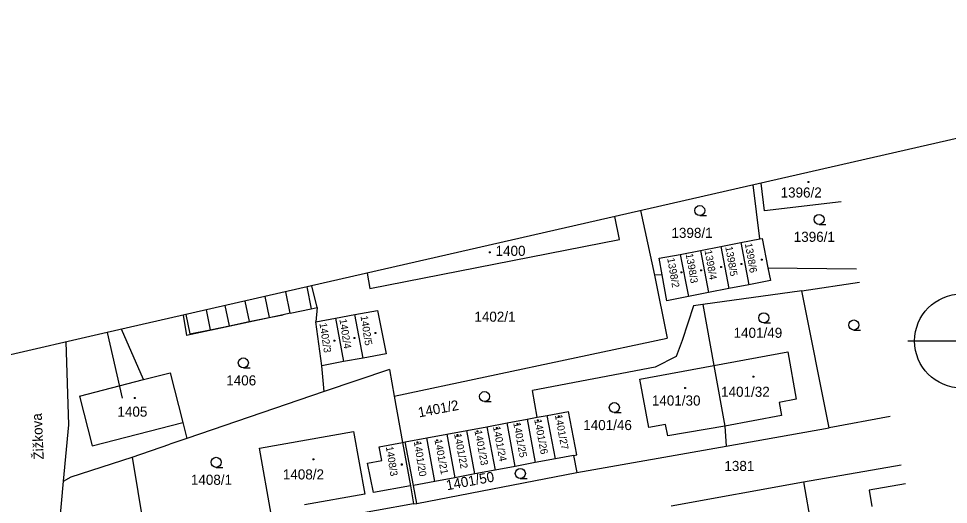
# Model space of a CAD drawing. Extents: x -805730 to -804640, y -1150889 to -1150366.
# Drawn here: x -804924.5 to -804785.9, y -1150438.4 to -1150366 of the extents above; entities that cross this region are included whole.
import ezdxf

# ---------------------------------------------------------------- set-up
doc = ezdxf.new("R2010")
doc.units = 0
for name, color, linetype in [('Default', 7, 'Continuous'), ('formát', 7, 'Continuous'), ('kn_celek - Cisla pozemkovych parcel', 7, 'Continuous'), ('kn_celek - Cisla stavebnich parcel', 7, 'Continuous'), ('kn_celek - Dalsi prvky mapy popis', 7, 'Continuous'), ('kn_celek - Hranice parcel', 7, 'Continuous'), ('kn_celek - Vnitrni kresby', 7, 'Continuous'), ('kn_celek - Znacky budov', 7, 'Continuous'), ('kn_celek - Znacky kultur', 7, 'Continuous')]:
    doc.layers.add(name, color=color, linetype=linetype)

# ---------------------------------------------------------------- blocks, each defined once
blk = doc.blocks.new('304')
at = {"layer": 'Default'}
blk.add_line((-0.1, 0), (9.9, 0), dxfattribs=at)
blk.add_circle((-0.1, 7.5), 7.5, dxfattribs=at)
blk = doc.blocks.new('402')
at = {"layer": 'Default'}
for p, q in [((-0.8, 0.8), (0.7, 0.8)), ((-0.8, 0.8), (-0.8, -0.7)), ((0.7, 0.8), (0.7, -0.7)), ((0.7, -0.7), (-0.8, -0.7))]:
    blk.add_line(p, q, dxfattribs=at)

msp = doc.modelspace()

# ---------------------------------------------------------------- linework, layer by layer
at = {"layer": 'formát'}
for p, q in [((-804706.6, -1150365.97), (-804911.33, -1150412.76)), ((-804911.33, -1150412.76), (-805116.05, -1150459.54)), ((-804911.33, -1150412.76), (-804909.1, -1150422.5)), ((-804791.95, -1150414), (-804775.95, -1150414))]:
    msp.add_line(p, q, dxfattribs=at)
msp.add_circle((-804783.95, -1150414), 7, dxfattribs=at)
at = {"layer": 'kn_celek - Hranice parcel'}
for p, q in [((-804814, -1150398.79), (-804815.01, -1150390.74)), ((-804813.34, -1150394.63), (-804813.84, -1150390.47)), ((-804801.9, -1150393.26), (-804813.34, -1150394.63)), ((-804831.82, -1150394.58), (-804829.73, -1150404.21)), ((-804834.96, -1150398.88), (-804835.65, -1150395.46)), ((-804872.14, -1150406.19), (-804834.96, -1150398.88)), ((-804816.85, -1150399.35), (-804814, -1150398.79)), ((-804814, -1150398.79), (-804813.67, -1150398.72)), ((-804813.67, -1150398.72), (-804812.81, -1150403.09)), ((-804822.88, -1150400.52), (-804819.85, -1150399.93)), ((-804819.85, -1150399.93), (-804816.85, -1150399.35)), ((-804819.85, -1150399.93), (-804818.64, -1150406.19)), ((-804816.85, -1150399.35), (-804815.64, -1150405.61)), ((-804829.01, -1150401.67), (-804825.87, -1150401.09)), ((-804828.57, -1150404.13), (-804829.01, -1150401.67)), ((-804825.87, -1150401.09), (-804822.88, -1150400.52)), ((-804825.87, -1150401.09), (-804824.66, -1150407.36)), ((-804822.88, -1150400.52), (-804821.67, -1150406.78)), ((-804812.81, -1150403.09), (-804808.43, -1150403.14)), ((-804812.81, -1150403.09), (-804812.44, -1150405)), ((-804808.43, -1150403.14), (-804799.62, -1150403.24)), ((-804872.57, -1150403.9), (-804872.14, -1150406.19)), ((-804828.57, -1150404.13), (-804829.73, -1150404.21)), ((-804829.73, -1150404.21), (-804827.82, -1150413.58)), ((-804827.86, -1150408.03), (-804828.57, -1150404.13)), ((-804881.57, -1150405.95), (-804880.9, -1150409.19)), ((-804880.03, -1150409), (-804880.8, -1150405.78)), ((-804815.64, -1150405.61), (-804818.64, -1150406.19)), ((-804812.44, -1150405), (-804815.64, -1150405.61)), ((-804807.76, -1150406.52), (-804799.16, -1150405.25)), ((-804887.83, -1150407.38), (-804887.18, -1150410.5)), ((-804884.02, -1150409.86), (-804884.69, -1150406.67)), ((-804824.66, -1150407.36), (-804827.86, -1150408.03)), ((-804821.67, -1150406.78), (-804824.66, -1150407.36)), ((-804807.76, -1150406.52), (-804822.52, -1150408.58)), ((-804818.64, -1150406.19), (-804821.67, -1150406.78)), ((-804803.69, -1150426.95), (-804807.76, -1150406.52)), ((-804893.09, -1150411.73), (-804893.71, -1150408.73)), ((-804890.78, -1150408.06), (-804890.14, -1150411.12)), ((-804823.89, -1150408.77), (-804825.57, -1150413.91)), ((-804822.52, -1150408.58), (-804823.89, -1150408.77)), ((-804822.52, -1150408.58), (-804820.89, -1150417.64)), ((-804900, -1150410.17), (-804899.47, -1150413.17)), ((-804899.59, -1150410.07), (-804898.99, -1150412.96)), ((-804885.07, -1150410.08), (-804899.47, -1150413.17)), ((-804896.55, -1150409.38), (-804895.94, -1150412.32)), ((-804887.18, -1150410.5), (-804885.07, -1150410.08)), ((-804884.02, -1150409.86), (-804885.07, -1150410.08)), ((-804884.02, -1150409.86), (-804880.89, -1150409.22)), ((-804880.9, -1150409.19), (-804880.03, -1150409)), ((-804880.9, -1150409.19), (-804880.89, -1150409.22)), ((-804880.03, -1150409), (-804880.21, -1150411.14)), ((-804877.29, -1150410.62), (-804874.37, -1150410.07)), ((-804874.37, -1150410.07), (-804870.99, -1150409.45)), ((-804873.16, -1150416.54), (-804874.37, -1150410.07)), ((-804870.99, -1150409.45), (-804869.72, -1150415.9)), ((-804893.09, -1150411.73), (-804890.14, -1150411.12)), ((-804890.14, -1150411.12), (-804887.18, -1150410.5)), ((-804880.21, -1150411.14), (-804877.29, -1150410.62)), ((-804879.29, -1150417.68), (-804880.21, -1150411.14)), ((-804877.29, -1150410.62), (-804876.08, -1150417.08)), ((-804905.91, -1150419.76), (-804909.16, -1150412.26)), ((-804898.99, -1150412.96), (-804895.94, -1150412.32)), ((-804895.94, -1150412.32), (-804893.09, -1150411.73)), ((-804917.04, -1150426.49), (-804917.43, -1150414.15)), ((-804868.52, -1150422.21), (-804827.82, -1150413.58)), ((-804825.57, -1150413.91), (-804826.47, -1150416.31)), ((-804820.89, -1150417.64), (-804809.86, -1150415.61)), ((-804809.86, -1150415.61), (-804808.62, -1150422.68)), ((-804876.08, -1150417.08), (-804879.29, -1150417.68)), ((-804873.16, -1150416.54), (-804876.08, -1150417.08)), ((-804869.72, -1150415.9), (-804873.16, -1150416.54)), ((-804826.47, -1150416.31), (-804829.6, -1150417.89)), ((-804878.94, -1150421.54), (-804879.29, -1150417.68)), ((-804869.23, -1150418.27), (-804878.94, -1150421.54)), ((-804869.23, -1150418.27), (-804868.52, -1150422.21)), ((-804829.6, -1150417.89), (-804847.92, -1150421.36)), ((-804831.91, -1150419.67), (-804820.89, -1150417.64)), ((-804820.89, -1150417.64), (-804819.25, -1150426.68)), ((-804905.91, -1150419.76), (-804901.92, -1150418.74)), ((-804901.92, -1150418.74), (-804900.03, -1150426.14)), ((-804830.58, -1150426.89), (-804831.91, -1150419.67)), ((-804878.94, -1150421.54), (-804899.42, -1150428.51)), ((-804868.52, -1150422.21), (-804867.28, -1150429.13)), ((-804847.21, -1150425.37), (-804847.92, -1150421.36)), ((-804808.62, -1150422.68), (-804811.11, -1150423.15)), ((-804811.11, -1150423.15), (-804810.77, -1150425.1)), ((-804848.71, -1150425.65), (-804847.21, -1150425.37)), ((-804847.21, -1150425.37), (-804845.71, -1150425.08)), ((-804845.71, -1150425.08), (-804842.53, -1150424.5)), ((-804844.5, -1150431.56), (-804845.71, -1150425.08)), ((-804841.29, -1150430.95), (-804842.53, -1150424.5)), ((-804810.77, -1150425.1), (-804819.25, -1150426.68)), ((-804794.59, -1150425.24), (-804803.69, -1150426.95)), ((-804917.82, -1150434.88), (-804917.04, -1150426.49)), ((-804900.03, -1150426.14), (-804899.42, -1150428.51)), ((-804857.69, -1150427.33), (-804854.69, -1150426.77)), ((-804854.69, -1150426.77), (-804851.7, -1150426.21)), ((-804854.69, -1150426.77), (-804853.48, -1150433.25)), ((-804851.7, -1150426.21), (-804848.71, -1150425.65)), ((-804850.49, -1150432.68), (-804851.7, -1150426.21)), ((-804848.71, -1150425.65), (-804847.49, -1150432.12)), ((-804828.08, -1150426.43), (-804830.58, -1150426.89)), ((-804827.74, -1150428.12), (-804828.08, -1150426.43)), ((-804819.25, -1150426.68), (-804827.74, -1150428.12)), ((-804819.25, -1150426.68), (-804819.04, -1150429.67)), ((-804888.61, -1150429.96), (-804874.58, -1150427.49)), ((-804874.58, -1150427.49), (-804872.92, -1150436.84)), ((-804863.67, -1150428.45), (-804860.68, -1150427.89)), ((-804860.68, -1150427.89), (-804857.69, -1150427.33)), ((-804860.68, -1150427.89), (-804859.47, -1150434.37)), ((-804856.48, -1150433.81), (-804857.69, -1150427.33)), ((-804819.04, -1150429.67), (-804803.69, -1150426.95)), ((-804907.58, -1150431.32), (-804901.97, -1150429.38)), ((-804899.42, -1150428.51), (-804901.97, -1150429.38)), ((-804870.75, -1150429.77), (-804867.28, -1150429.13)), ((-804867.28, -1150429.13), (-804866.87, -1150429.05)), ((-804866.87, -1150429.05), (-804863.67, -1150428.45)), ((-804865.66, -1150435.52), (-804866.87, -1150429.05)), ((-804862.46, -1150434.93), (-804863.67, -1150428.45)), ((-804886.88, -1150439.82), (-804888.61, -1150429.96)), ((-804870.36, -1150431.83), (-804870.75, -1150429.77)), ((-804841.79, -1150431.04), (-804841.29, -1150430.95)), ((-804841.31, -1150433.62), (-804819.04, -1150429.67)), ((-804916.66, -1150434.24), (-804907.58, -1150431.32)), ((-804907.58, -1150431.32), (-804905.24, -1150445.34)), ((-804872.48, -1150432.21), (-804870.36, -1150431.83)), ((-804871.63, -1150436.6), (-804872.48, -1150432.21)), ((-804847.49, -1150432.12), (-804850.49, -1150432.68)), ((-804844.5, -1150431.56), (-804847.49, -1150432.12)), ((-804841.79, -1150431.04), (-804844.5, -1150431.56)), ((-804841.79, -1150431.04), (-804841.31, -1150433.62)), ((-804865.16, -1150438.2), (-804841.31, -1150433.62)), ((-804853.48, -1150433.25), (-804856.48, -1150433.81)), ((-804850.49, -1150432.68), (-804853.48, -1150433.25)), ((-804807.5, -1150434.98), (-804792.94, -1150432.45)), ((-804918.43, -1150441.58), (-804917.82, -1150434.88)), ((-804917.82, -1150434.88), (-804916.66, -1150434.24)), ((-804862.46, -1150434.93), (-804865.66, -1150435.52)), ((-804859.47, -1150434.37), (-804862.46, -1150434.93)), ((-804856.48, -1150433.81), (-804859.47, -1150434.37)), ((-804827.24, -1150438.54), (-804807.5, -1150434.98)), ((-804807.5, -1150434.98), (-804801.17, -1150471.28)), ((-804866.11, -1150435.6), (-804871.63, -1150436.6)), ((-804866.11, -1150435.6), (-804865.63, -1150438.29)), ((-804865.16, -1150438.2), (-804865.66, -1150435.52)), ((-804792.3, -1150435.27), (-804797.73, -1150436.25)), ((-804797.73, -1150436.25), (-804797.3, -1150438.65)), ((-804872.92, -1150436.84), (-804881.87, -1150438.42)), ((-804865.63, -1150438.29), (-804876.69, -1150440.25)), ((-804865.63, -1150438.29), (-804865.16, -1150438.2))]:
    msp.add_line(p, q, dxfattribs=at)
at = {"layer": 'kn_celek - Vnitrni kresby'}
for p, q in [((-804915.42, -1150422.21), (-804905.91, -1150419.76)), ((-804915.42, -1150422.21), (-804913.53, -1150429.64)), ((-804913.53, -1150429.64), (-804900.03, -1150426.14)), ((-804867.28, -1150429.13), (-804866.11, -1150435.6))]:
    msp.add_line(p, q, dxfattribs=at)

# ---------------------------------------------------------------- block references
at = {"layer": 'kn_celek - Znacky budov', "xscale": 0.1, "yscale": 0.10000000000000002}
for p in [(-804806.8, -1150390.31), (-804854.29, -1150400.81), (-804813.72, -1150401.88), (-804819.79, -1150402.99), (-804816.76, -1150402.54), (-804825.71, -1150403.78), (-804822.78, -1150403.47), (-804871.32, -1150412.82), (-804877.42, -1150413.97), (-804874.46, -1150413.55), (-804814.98, -1150419.33), (-804825.16, -1150421.01), (-804907.21, -1150422.48), (-804844.02, -1150425.23), (-804850.18, -1150426.37), (-804847.13, -1150425.82), (-804859.1, -1150428.04), (-804856.13, -1150427.49), (-804853.22, -1150426.96), (-804865.05, -1150429.13), (-804862.13, -1150428.79), (-804880.59, -1150431.63), (-804867.42, -1150432.41)]:
    msp.add_blockref('402', p, dxfattribs=at)
at = {"layer": 'kn_celek - Znacky kultur', "xscale": 0.1, "yscale": 0.10000000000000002}
for p in [(-804822.96, -1150395.32), (-804805.18, -1150396.63), (-804813.42, -1150411.31), (-804800, -1150412.37), (-804891, -1150418.02), (-804855.04, -1150423.04), (-804835.7, -1150424.68), (-804895.05, -1150432.83), (-804849.71, -1150434.5)]:
    msp.add_blockref('304', p, dxfattribs=at)

# ---------------------------------------------------------------- texts
at = {"layer": 'kn_celek - Cisla pozemkovych parcel'}
for s, p in [('1398/1', (-804827.19, -1150398.64)), ('1396/1', (-804808.96, -1150399.23)), ('1402/1', (-804856.57, -1150411.13)), ('1401/49', (-804817.93, -1150413.53)), ('1406', (-804893.56, -1150420.62)), ('1401/46', (-804840.34, -1150427.28)), ('1381', (-804819.3, -1150433.37)), ('1408/1', (-804898.83, -1150435.43))]:
    msp.add_text(s, height=1.5, dxfattribs=at).set_placement(p)
for s, rotation, p in [('1401/2', 10.8, (-804864.82, -1150425.4)), ('1401/50', 10.7001, (-804860.64, -1150436.26))]:
    msp.add_text(s, height=1.5, rotation=rotation, dxfattribs=at).set_placement(p)
at = {"layer": 'kn_celek - Cisla stavebnich parcel'}
for s, p in [('1396/2', (-804810.92, -1150392.63)), ('1400', (-804853.41, -1150401.32)), ('1401/32', (-804819.79, -1150422.32)), ('1401/30', (-804830.11, -1150423.62)), ('1405', (-804909.78, -1150425.28)), ('1408/2', (-804885.12, -1150434.63))]:
    msp.add_text(s, height=1.5, dxfattribs=at).set_placement(p)
for s, rotation, p in [('1398/5', 279.9, (-804819.17, -1150399.99)), ('1398/6', 279.9, (-804816.26, -1150399.49)), ('1398/2', 279.9, (-804827.83, -1150401.71)), ('1398/3', 279.9, (-804825.07, -1150401.05)), ('1398/4', 279.9, (-804822.26, -1150400.53)), ('1402/3', 279, (-804879.67, -1150411.38)), ('1402/4', 279, (-804876.69, -1150410.79)), ('1402/5', 279, (-804873.55, -1150410.3)), ('1401/27', 280.8, (-804844.58, -1150425.06)), ('1401/24', 280.8, (-804853.8, -1150426.8)), ('1401/25', 280.8, (-804850.78, -1150426.22)), ('1401/26', 280.8, (-804847.65, -1150425.74)), ('1401/22', 280.8, (-804859.6, -1150427.88)), ('1401/23', 280.8, (-804856.56, -1150427.4)), ('1401/20', 279, (-804865.6, -1150429)), ('1401/21', 280.8, (-804862.52, -1150428.75)), ('1408/3', 279, (-804869.77, -1150429.77))]:
    msp.add_text(s, height=1.1, rotation=rotation, dxfattribs=at).set_placement(p)
at = {"layer": 'kn_celek - Dalsi prvky mapy popis'}
msp.add_text('Žižkova', height=1.5, rotation=92.5771, dxfattribs=at).set_placement((-804920.76, -1150431.64))

doc.saveas('drawing.dxf')
